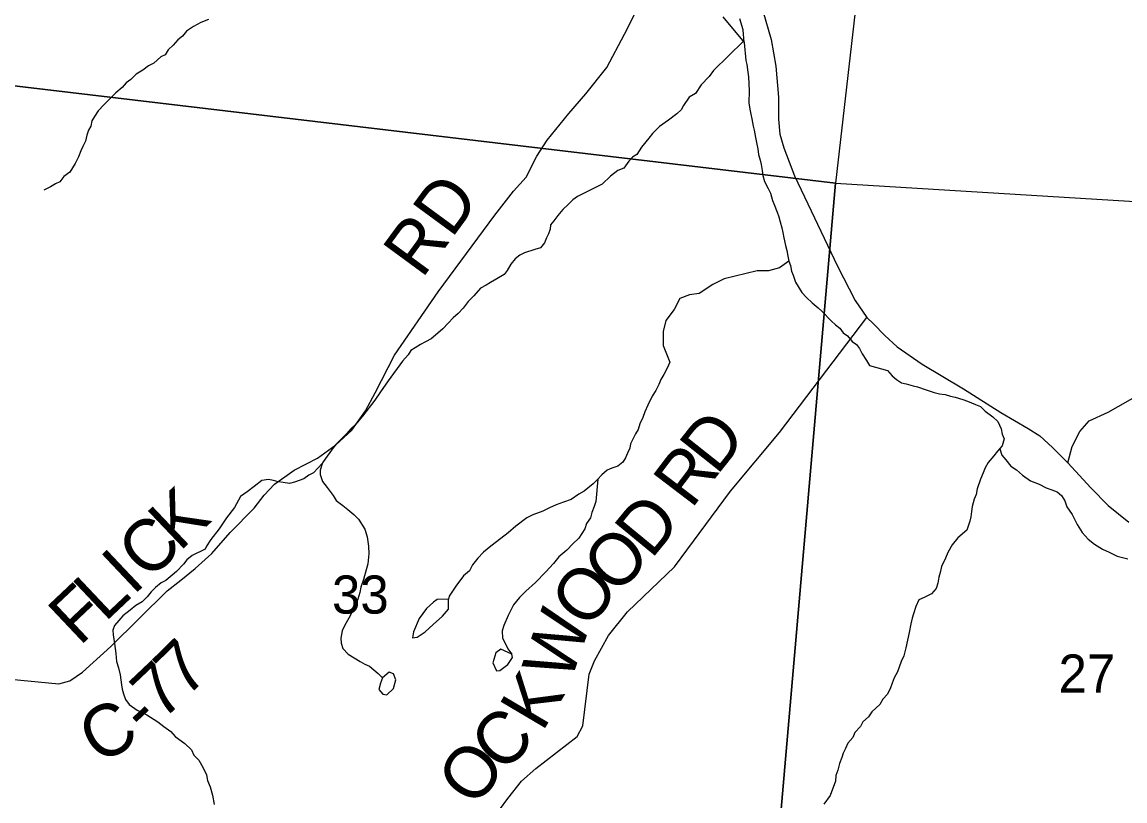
# Model space of a CAD drawing. Extents: x 0 to 34, y 0 to 22.
# Drawn here: x 5.755 to 6.965, y 19.391 to 20.246 of the extents above; entities that cross this region are included whole.
import ezdxf

# ---------------------------------------------------------------- set-up
doc = ezdxf.new("R2010")
doc.units = 0
for name, color, linetype in [('Default', 7, 'Continuous'), ('GM_X_County_Road', 7, 'Continuous'), ('GM_X_County_Road_Text', 7, 'Continuous'), ('GM_X_Minor_Lake', 7, 'Continuous'), ('GM_X_Minor_River', 7, 'Continuous'), ('GM_X_Section', 7, 'Continuous'), ('GM_X_Section_Text', 7, 'Continuous')]:
    doc.layers.add(name, color=color, linetype=linetype)

msp = doc.modelspace()

# ---------------------------------------------------------------- linework, layer by layer
at = {"layer": 'Default'}
msp.add_lwpolyline([(7.4473, 20.9), (6.898, 20.9), (6.8905, 20.8862), (6.8831, 20.8788), (6.8772, 20.8714), (6.8677, 20.8519), (6.8545, 20.8401), (6.8379, 20.8269), (6.8281, 20.8138), (6.8084, 20.7969), (6.7976, 20.7888), (6.7851, 20.7759), (6.7734, 20.7614), (6.7572, 20.7474), (6.7425, 20.7348), (6.7286, 20.7246), (6.7247, 20.7201), (6.7215, 20.7141), (6.6475, 20.0689), (7.4124, 20.0219)], close=True, dxfattribs=at)
at = {"layer": 'GM_X_County_Road'}
for points in [[(5.7304, 19.5254), (5.7948, 19.5193), (5.8071, 19.5227), (5.821, 19.5322), (5.8519, 19.5604), (5.9138, 19.6215), (5.929, 19.6332), (5.9446, 19.6459), (5.9629, 19.6624), (5.983, 19.6854), (6.0093, 19.7122), (6.0204, 19.7263), (6.0318, 19.7385), (6.0531, 19.7537), (6.0789, 19.767), (6.0991, 19.7815), (6.1167, 19.7977), (6.1314, 19.8188), (6.1423, 19.8386), (6.1634, 19.8801), (6.2115, 19.9494), (6.2735, 20.0335), (6.294, 20.0599), (6.308, 20.0752), (6.3197, 20.0983), (6.3309, 20.116), (6.3546, 20.1453), (6.3735, 20.1666), (6.3964, 20.1955), (6.4159, 20.2324), (6.4425, 20.2857)], [(6.5678, 20.2579), (6.5768, 20.2264), (6.5818, 20.197), (6.5848, 20.163), (6.5848, 20.1389), (6.5863, 20.1227), (6.5906, 20.1074), (6.6023, 20.0767), (6.6497, 19.9775), (6.669, 19.9401), (6.6818, 19.9214), (6.6891, 19.9143), (6.7017, 19.9017), (6.7153, 19.8891), (6.7426, 19.8701), (6.7878, 19.8429), (6.8289, 19.8172), (6.8591, 19.7997), (6.8719, 19.7914), (6.8858, 19.7787), (6.9026, 19.7617), (6.9279, 19.7346), (6.9469, 19.7152), (6.9695, 19.6969)], [(6.9026, 19.7617), (6.9073, 19.7799), (6.9157, 19.7961), (6.9261, 19.8081), (6.9469, 19.8173), (7.0642, 19.8839), (7.076, 19.8949), (7.0842, 19.9057), (7.0892, 19.9185), (7.0896, 19.9329), (7.0855, 19.949), (7.0773, 19.9698), (7.0607, 20.0003), (7.0591, 20.0106), (7.057, 20.0277), (7.0632, 20.103), (7.0653, 20.1145), (7.0701, 20.1296), (7.1104, 20.2391)], [(6.2695, 19.3685), (6.2877, 19.3934), (6.3028, 19.4126), (6.3184, 19.4266), (6.3639, 19.4616), (6.3703, 19.4731), (6.3771, 19.5299), (6.3829, 19.5445), (6.3982, 19.5725), (6.4192, 19.5984), (6.4708, 19.6477), (6.5323, 19.7307), (6.586, 19.7951), (6.6818, 19.9214)]]:
    msp.add_lwpolyline(points, dxfattribs=at)
at = {"layer": 'GM_X_Minor_Lake'}
for points in [[(6.2103, 19.612), (6.2061, 19.609), (6.1987, 19.602), (6.1904, 19.5912), (6.1843, 19.5766), (6.183, 19.5698), (6.1883, 19.5704), (6.1969, 19.5766), (6.2058, 19.5843), (6.2159, 19.5936), (6.2226, 19.6014), (6.2225, 19.6122)], [(6.2225, 19.6122), (6.2103, 19.612)], [(6.28, 19.5573), (6.2745, 19.5533), (6.2712, 19.5423), (6.2755, 19.5335), (6.279, 19.5341), (6.2879, 19.5404), (6.293, 19.5482), (6.2923, 19.5518)], [(6.2923, 19.5518), (6.28, 19.5573)], [(6.1502, 19.5259), (6.1479, 19.5201), (6.1462, 19.5133), (6.1506, 19.5079), (6.1548, 19.5074), (6.1622, 19.5144), (6.1647, 19.5239), (6.1622, 19.5304), (6.1577, 19.532)], [(6.1577, 19.532), (6.1502, 19.5259)]]:
    msp.add_lwpolyline(points, dxfattribs=at)
at = {"layer": 'GM_X_Minor_River'}
for points in [[(5.9594, 20.2482), (5.9509, 20.2452), (5.9429, 20.2408), (5.9352, 20.2356), (5.9305, 20.23), (5.9255, 20.2262), (5.9204, 20.2202), (5.915, 20.215), (5.9118, 20.2097), (5.9069, 20.2075)], [(6.5237, 20.2514), (6.5474, 20.2232)], [(6.5474, 20.2232), (6.5462, 20.2369), (6.5423, 20.2491)], [(6.5464, 20.2244), (6.5134, 20.1923), (6.5087, 20.1859), (6.5002, 20.1765), (6.4939, 20.1671), (6.487, 20.163), (6.4807, 20.154), (6.4779, 20.1491), (6.4733, 20.145), (6.464, 20.1379), (6.4544, 20.1308), (6.4466, 20.1233), (6.4424, 20.118), (6.4346, 20.1083), (6.4295, 20.1003), (6.4245, 20.0974), (6.4206, 20.0929), (6.4151, 20.0853), (6.4086, 20.0828), (6.4005, 20.0764), (6.3912, 20.0678), (6.3774, 20.0608), (6.3693, 20.0568), (6.3643, 20.0542), (6.3593, 20.0504), (6.3539, 20.0452), (6.3481, 20.04), (6.3426, 20.0332), (6.3383, 20.0275), (6.3348, 20.023), (6.3343, 20.0181), (6.3323, 20.0132), (6.3304, 20.0086), (6.328, 20.0033), (6.3237, 19.9977), (6.3176, 19.9959), (6.3061, 19.9923), (6.3011, 19.9897), (6.2957, 19.9859), (6.291, 19.9799), (6.2871, 19.9731), (6.2836, 19.9686), (6.2759, 19.9638), (6.2689, 19.9597), (6.2639, 19.9567), (6.2578, 19.9534), (6.2504, 19.9452), (6.2442, 19.9388), (6.2387, 19.9316), (6.2333, 19.9256), (6.2279, 19.9211), (6.2224, 19.9151), (6.2166, 19.9088), (6.2085, 19.902), (6.2035, 19.8979), (6.1973, 19.8946), (6.1919, 19.8916), (6.1862, 19.8879), (6.1812, 19.8853), (6.1784, 19.8804), (6.1722, 19.8733)], [(6.5474, 20.2232), (6.549, 20.2035), (6.55, 20.199), (6.5514, 20.1905), (6.5521, 20.1856), (6.5523, 20.1776), (6.5526, 20.17), (6.5523, 20.157), (6.5533, 20.1501), (6.5544, 20.1444), (6.5558, 20.1394), (6.5572, 20.1314), (6.5582, 20.1268), (6.5596, 20.1188), (6.561, 20.1115), (6.5621, 20.1066), (6.5631, 20.1001), (6.5649, 20.094), (6.5659, 20.0894), (6.567, 20.0825), (6.5676, 20.0771), (6.5694, 20.0706), (6.5735, 20.063), (6.576, 20.0576), (6.5785, 20.0499), (6.58, 20.0453), (6.5833, 20.0369), (6.5854, 20.0319), (6.5869, 20.0262), (6.5887, 20.0197), (6.5897, 20.0147), (6.5907, 20.0086), (6.5925, 20.0002), (6.5939, 19.9948), (6.5953, 19.9887), (6.5964, 19.983), (6.5982, 19.9784), (6.5992, 19.9723), (6.601, 19.9677), (6.6036, 19.96), (6.6106, 19.9488), (6.6158, 19.9434), (6.6218, 19.9376), (6.6285, 19.9318), (6.633, 19.9279), (6.6428, 19.9178), (6.6476, 19.9132), (6.6521, 19.9097), (6.6558, 19.9047), (6.6607, 19.9012), (6.6659, 19.895), (6.6705, 19.8919), (6.6738, 19.8872), (6.6767, 19.8815), (6.6815, 19.8742), (6.6849, 19.8688)], [(5.9069, 20.2075), (5.8991, 20.2004), (5.8934, 20.1974), (5.8872, 20.1926), (5.8799, 20.1885), (5.874, 20.1825), (5.8687, 20.1788), (5.8644, 20.1739), (5.8574, 20.1679), (5.8493, 20.16), (5.8446, 20.1552), (5.838, 20.148), (5.8341, 20.142), (5.8313, 20.1371), (5.8301, 20.1314), (5.8274, 20.1269), (5.8257, 20.1216), (5.8241, 20.1147), (5.8213, 20.1091), (5.8189, 20.1041), (5.8165, 20.0977), (5.813, 20.0905), (5.8099, 20.0856), (5.8071, 20.0807), (5.8005, 20.0759), (5.7959, 20.0702), (5.7913, 20.068), (5.7859, 20.0647), (5.7786, 20.061)], [(6.5964, 19.983), (6.5859, 19.9758), (6.5738, 19.9727), (6.5616, 19.9727), (6.5252, 19.9636), (6.513, 19.9575), (6.4978, 19.9477), (6.4872, 19.9461), (6.4765, 19.9423), (6.4704, 19.9302), (6.4613, 19.918), (6.4583, 19.9059), (6.4583, 19.8937), (6.4583, 19.8907)], [(6.4583, 19.8907), (6.4655, 19.8723), (6.4626, 19.8659), (6.4589, 19.8588), (6.4557, 19.8532), (6.4536, 19.848), (6.4504, 19.8412), (6.4463, 19.8349), (6.4414, 19.8252), (6.4382, 19.8177), (6.436, 19.8117), (6.4328, 19.8046), (6.431, 19.7986), (6.4278, 19.7938), (6.425, 19.7878), (6.4225, 19.7829), (6.4216, 19.778), (6.4191, 19.7724), (6.4171, 19.7675), (6.4142, 19.7627), (6.4084, 19.7583), (6.4018, 19.7559), (6.3968, 19.7538), (6.391, 19.7487), (6.3862, 19.7435), (6.3815, 19.7387), (6.3717, 19.7307), (6.3656, 19.7275), (6.3574, 19.7217), (6.3489, 19.7186), (6.3409, 19.7158), (6.3335, 19.7126), (6.3262, 19.7087), (6.3154, 19.7049), (6.3085, 19.7014), (6.2964, 19.6923), (6.2882, 19.685), (6.28, 19.6788), (6.269, 19.6704), (6.2612, 19.6638), (6.2549, 19.6572), (6.249, 19.6498), (6.2457, 19.6435), (6.2391, 19.638), (6.2351, 19.6324), (6.2315, 19.6276), (6.2271, 19.6209), (6.2235, 19.6154), (6.2225, 19.6122)], [(6.1722, 19.8733), (6.1565, 19.8518), (6.1481, 19.8399), (6.1417, 19.8306), (6.1282, 19.8129), (6.1211, 19.8044), (6.1156, 19.7992), (6.1112, 19.7941), (6.1037, 19.7867), (6.0982, 19.7812), (6.0942, 19.7757), (6.0875, 19.7668), (6.0843, 19.7619), (6.0817, 19.754), (6.0819, 19.7491), (6.0843, 19.7414), (6.0894, 19.7348), (6.096, 19.7262), (6.0992, 19.7204), (6.1066, 19.7152), (6.1121, 19.7108), (6.1188, 19.7053), (6.1239, 19.7001), (6.1307, 19.6889), (6.1335, 19.6808), (6.1347, 19.6705), (6.1351, 19.6621), (6.134, 19.6511), (6.1292, 19.6338), (6.1266, 19.6256), (6.1253, 19.6195), (6.1232, 19.6124), (6.1186, 19.6019), (6.1133, 19.5914), (6.1089, 19.5836), (6.106, 19.5776), (6.1046, 19.5693), (6.1048, 19.564), (6.1065, 19.5582), (6.1127, 19.5519), (6.119, 19.5479), (6.1257, 19.5439), (6.1309, 19.541), (6.1358, 19.5386), (6.1406, 19.5346), (6.1454, 19.5307), (6.1502, 19.5259)], [(6.6849, 19.8688), (6.7047, 19.8632), (6.7095, 19.8573), (6.7143, 19.8534), (6.7198, 19.8498), (6.7251, 19.8484), (6.7326, 19.8463), (6.7375, 19.8453), (6.7469, 19.842), (6.7559, 19.839), (6.7616, 19.8377), (6.768, 19.8367), (6.7736, 19.835), (6.7789, 19.834), (6.7872, 19.8315), (6.7924, 19.8294), (6.801, 19.826), (6.8066, 19.8236), (6.8118, 19.8185), (6.8203, 19.8125), (6.8258, 19.8073), (6.8293, 19.7992), (6.8306, 19.7935), (6.8327, 19.7881), (6.8306, 19.7806), (6.8254, 19.7747), (6.8211, 19.7695), (6.8151, 19.7621), (6.8119, 19.7565), (6.8094, 19.7509), (6.8065, 19.7438), (6.8031, 19.7332), (6.8018, 19.7272), (6.7997, 19.722), (6.7975, 19.7141), (6.7966, 19.7084), (6.796, 19.7027), (6.7951, 19.6978), (6.7917, 19.688), (6.7819, 19.6796), (6.7756, 19.6719), (6.7707, 19.6633), (6.7682, 19.6573), (6.7637, 19.648), (6.7624, 19.6415), (6.761, 19.6363), (6.7597, 19.6299), (6.758, 19.6238), (6.7528, 19.6183), (6.7447, 19.614), (6.7389, 19.6116), (6.7356, 19.6041), (6.7331, 19.5962), (6.7318, 19.5913), (6.73, 19.5853), (6.7282, 19.5758), (6.7264, 19.5672), (6.7246, 19.5589), (6.7224, 19.5502), (6.7195, 19.5438), (6.7157, 19.5326), (6.712, 19.5259), (6.7096, 19.5202), (6.7079, 19.515), (6.7046, 19.5082), (6.6995, 19.5027), (6.6962, 19.4968), (6.6872, 19.4887), (6.6836, 19.4831), (6.6773, 19.4776), (6.6749, 19.4724), (6.6686, 19.4658), (6.6665, 19.4605), (6.661, 19.4543), (6.6585, 19.4483), (6.656, 19.4434), (6.6544, 19.4385), (6.6518, 19.4318), (6.6501, 19.4246), (6.648, 19.4186), (6.6474, 19.4126), (6.6415, 19.3968), (6.6347, 19.3872)], [(6.8277, 19.7773), (6.8302, 19.7703), (6.8346, 19.7652), (6.8401, 19.7582), (6.846, 19.7542), (6.8526, 19.7482), (6.8615, 19.7422), (6.8709, 19.7385), (6.8787, 19.7344), (6.8851, 19.7323), (6.8907, 19.7302), (6.8955, 19.7259), (6.8991, 19.72), (6.9015, 19.7135), (6.9073, 19.7053), (6.9126, 19.6941), (6.9184, 19.6855), (6.925, 19.6781), (6.9316, 19.6725), (6.9406, 19.6673), (6.9477, 19.664), (6.9566, 19.6595), (6.9683, 19.6564)], [(6.084, 19.7612), (6.0744, 19.7509), (6.0694, 19.7484), (6.0639, 19.7444), (6.0535, 19.7406), (6.0482, 19.7392), (6.041, 19.7403), (6.0357, 19.7412), (6.0305, 19.7425), (6.0252, 19.7435), (6.0176, 19.7426), (6.0094, 19.736), (6.0016, 19.7302), (5.9945, 19.7248), (5.9877, 19.7128), (5.9789, 19.7017), (5.9709, 19.6895), (5.9618, 19.6776), (5.957, 19.6706), (5.9555, 19.667)], [(6.3865, 19.7438), (6.3843, 19.7196), (6.3826, 19.714), (6.38, 19.7072), (6.3787, 19.7016), (6.3743, 19.6953), (6.3722, 19.6893), (6.3658, 19.6792), (6.3591, 19.673), (6.3524, 19.666), (6.3438, 19.6587), (6.3379, 19.6513), (6.3296, 19.6421), (6.3182, 19.6307), (6.3076, 19.6212), (6.3005, 19.6142), (6.2942, 19.6061), (6.2881, 19.5945), (6.2835, 19.5833), (6.2814, 19.5776), (6.2819, 19.5693), (6.2851, 19.5634), (6.2879, 19.5576), (6.2923, 19.5518)], [(5.9555, 19.667), (5.9414, 19.6601), (5.9356, 19.6554), (5.9316, 19.6505), (5.9241, 19.6428), (5.9124, 19.6326), (5.9074, 19.6301), (5.9011, 19.625), (5.8964, 19.6202), (5.892, 19.615), (5.8865, 19.6095), (5.8795, 19.6052), (5.8733, 19.6001), (5.8651, 19.5939), (5.8607, 19.5888), (5.856, 19.5832), (5.8543, 19.5783), (5.8545, 19.573), (5.8561, 19.5638), (5.8576, 19.5528), (5.8581, 19.544), (5.8605, 19.5371), (5.8621, 19.5294), (5.8636, 19.5184), (5.8646, 19.5134), (5.8659, 19.5084), (5.868, 19.5022), (5.872, 19.4968), (5.8809, 19.4904), (5.8917, 19.4855), (5.9036, 19.4778), (5.9103, 19.4727), (5.9177, 19.4671), (5.9228, 19.4616), (5.9332, 19.454), (5.9405, 19.4469), (5.943, 19.4411), (5.9485, 19.4356), (5.9535, 19.4271), (5.957, 19.4194), (5.9583, 19.4132), (5.9611, 19.4063), (5.9635, 19.3971), (5.9654, 19.3871)]]:
    msp.add_lwpolyline(points, dxfattribs=at)
at = {"layer": 'GM_X_Section'}
msp.add_lwpolyline([(6.7215, 20.7141), (6.6475, 20.0689), (5.6809, 20.1832)], dxfattribs=at)
for points in [[(5.6809, 20.1832), (6.6475, 20.0689), (6.5612, 19.0743), (5.5723, 19.1942)], [(6.6475, 20.0689), (7.4124, 20.0219), (7.3629, 19.0139), (6.5612, 19.0743)]]:
    msp.add_lwpolyline(points, close=True, dxfattribs=at)

# ---------------------------------------------------------------- texts
at = {"layer": 'GM_X_County_Road_Text'}
for s, height, rotation, p in [('RD', 0.05682, 53.7194, (6.1935, 19.9629)), ('D', 0.0568, 51.608, (6.5173, 19.7471)), ('R', 0.0568, 52.7101, (6.4892, 19.7102)), ('K', 0.0568, 43.5895, (5.9274, 19.6636)), ('D', 0.0568, 50.5426, (6.4452, 19.6552)), ('C', 0.0568, 43.3701, (5.8933, 19.6314)), ('O', 0.0568, 44.6059, (6.4052, 19.6154)), ('I', 0.0568, 43.3711, (5.8763, 19.6154)), ('L', 0.0568, 43.3664, (5.8454, 19.5862)), ('O', 0.0568, 51.678, (6.3755, 19.5775)), ('F', 0.0568, 43.3703, (5.8176, 19.5599)), ('W', 0.0568, 70.7782, (6.3562, 19.5197)), ('7', 0.0568, 44.4283, (5.934, 19.5025)), ('7', 0.0568, 43.43, (5.9078, 19.4777)), ('K', 0.0568, 59.402, (6.3256, 19.4655)), ('C', 0.0568, 30.0905, (5.8388, 19.4298)), ('-', 0.0568, 43.0083, (5.8904, 19.4615)), ('C', 0.0568, 43.0449, (6.2804, 19.4199)), ('O', 0.0568, 52.905, (6.252, 19.382))]:
    msp.add_text(s, height=height, rotation=rotation, dxfattribs=at).set_placement(p)
at = {"layer": 'GM_X_Section_Text'}
for s, p in [('33', (6.0948, 19.5964)), ('27', (6.8923, 19.5097))]:
    msp.add_text(s, height=0.04186, rotation=0, dxfattribs=at).set_placement(p)

doc.saveas('drawing.dxf')
